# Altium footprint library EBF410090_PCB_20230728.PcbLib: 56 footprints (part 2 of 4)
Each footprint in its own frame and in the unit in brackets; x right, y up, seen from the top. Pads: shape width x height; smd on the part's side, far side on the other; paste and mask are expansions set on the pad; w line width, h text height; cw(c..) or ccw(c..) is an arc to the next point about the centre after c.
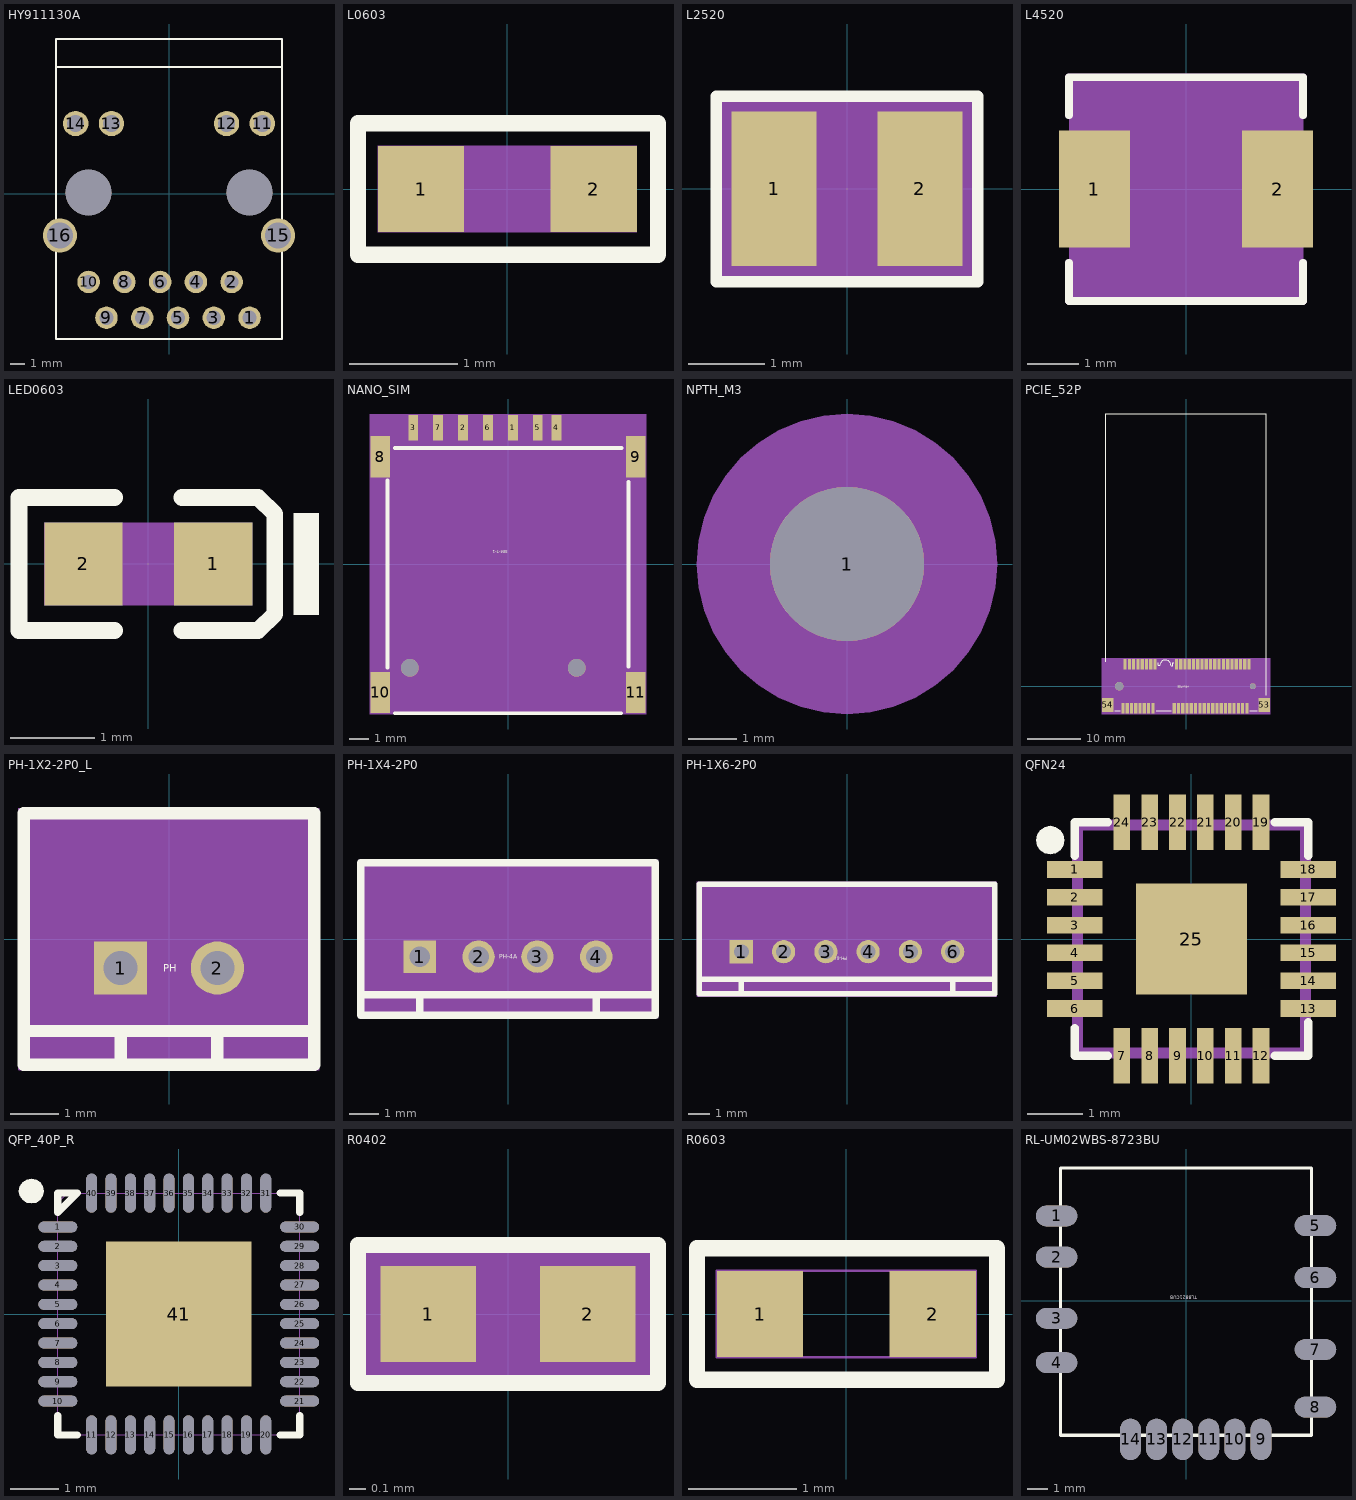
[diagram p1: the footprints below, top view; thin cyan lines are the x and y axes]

## HY911130A [mm] "HY911130A"
pads (18):
  round 1.6 / inner round 1.524 / far side round 1.6 hole 1: 1(5.72,-8.79) 2(4.45,-6.25) 3(3.18,-8.79) 4(1.91,-6.25) 5(0.64,-8.79) 6(-0.63,-6.25) 7(-1.9,-8.79) 8(-3.17,-6.25) 9(-4.44,-8.79)
  round 1.6 hole 1: 10(-5.71,-6.25)
  round 1.8 / inner round 1.524 / far side round 1.8 hole 1.2: 11(6.625,5) 12(4.085,5) 13(-4.085,5) 14(-6.625,5)
  round 2.43 hole 1.83: 15(7.745,-2.95) 16(-7.745,-2.95)
  round 3.25 hole 3.25 unplated: ""(-5.715,0.1) ""(5.715,0.1)
Top Overlay:
  lines w0.15: -8.02,11 8.02,11 8.02,9 ; -8.02,11 -8.02,-10.3 8.02,-10.3 8.02,9 ; -8.02,11 -8.02,9 8.02,9
Bottom Overlay:
  drawing of 14 lines, arcs and shapes, not listed
Mechanical 16:
  text "15" at 6.932,-2.95 h1.02
  text "16" at -8.558,-2.95 h1.02

## L0603 [mil] "L0603"
pads (2):
  rect 31.5x31.5 smd: 1(-31.5,0) 2(31.5,0)
Top Overlay:
  lines w6: -54.5,-24 -54.5,24 55,24 55,-24 -54.5,-24
Top 3D Body:
  region: -47.24,-15.75 -47.24,15.75 47.24,15.75 47.24,-15.75
3D body: height 150, standoff 0, extent -47.24,-15.75 47.24,15.75

## L2520 [mil] "L2520"
pads (2):
  rect 44x80 smd: 1(-37.75,0) 2(37.75,0)
Top Overlay:
  lines w6: -67.68,-48.15 -67.67,-48.15 67.67,-48.15 67.67,47.92 -67.68,47.92 -67.68,-48.15
Top 3D Body:
  region: -65,-45 65,-45 65,45 -65,45
Mechanical 16:
  text "2" at 33.03,0 h11.81
  text "1" at -42.47,0 h11.81
3D body: height 150, standoff 0, extent -65,-45 65,45

## L4520 [mm] "L4520"
pads (2):
  rect 1.4x2.3 smd: 1(-1.803,-0.003) 2(1.798,-0.003)
Top Overlay:
  lines w0.15: -2.303,-1.453 -2.303,-2.202 2.297,-2.202 2.297,-1.453 ; -2.303,1.448 -2.303,2.197 2.297,2.197 2.297,1.448
Top 3D Body:
  region: -2.303,-2.202 -2.303,2.202 2.303,2.202 2.303,-2.202
Mechanical 16:
  text "1" at -2.057,-0.003 h0.64
  text "2" at 1.544,-0.003 h0.64
Top Assembly:
  lines w0.15: -2.303,-1.453 -2.303,-2.202 2.297,-2.202 2.297,-1.453 ; -2.303,1.448 -2.303,2.197 2.297,2.197 2.297,1.448
3D body: height 3.81, standoff 0, extent -2.303,-2.202 2.303,2.202

## LED0603 [mm] "LED0603"
pads (2):
  rect 0.93x0.98 smd: 1(0.77,0) 2(-0.77,0)
Top Overlay:
  dashed: 1.725,-0.6 2.025,-0.6 2.025,0.6 1.725,0.6
  lines w0.2: -0.4,-0.79 -1.535,-0.79 -1.535,0.79 -0.4,0.79 ; 0.4,-0.79 1.3,-0.79 1.5,-0.597 1.5,0.597 1.3,0.79 0.4,0.79
Top 3D Body:
  region: -1.235,-0.49 1.235,-0.49 1.235,0.49 -1.235,0.49
Mechanical 16:
  text "2" at -0.77,-0.254 h0.64
  text "1" at 0.77,-0.254 h0.64
3D body: height 3.81, standoff 0, extent -1.235,-0.49 1.235,0.49

## NANO_SIM [mm] "NANO_SIM"
pads (13):
  rect 0.5x1.3 smd: 1(0.25,6.94) 2(-2.29,6.94) 3(-4.83,6.94) 4(2.47,6.94) 5(1.52,6.94) 6(-1.02,6.94) 7(-3.56,6.94)
  rect 1x2.1 smd: 8(-6.5,5.46) 9(6.5,5.46) 10(-6.5,-6.54) 11(6.5,-6.54)
  round 0.9 hole 0.9 unplated: ""(-5,-5.29) ""(3.5,-5.29)
Top Overlay:
  lines w0.2: -6.145,-5.267 -6.145,4.247 ; -5.756,5.9 5.784,5.9 ; -5.749,-7.6 0,-7.6 5.749,-7.6 ; 6.145,-5.215 6.145,4.189
  text "SIM-7-1" at 0,0.703 h0.15
Top 3D Body:
  region: -7.05,-7.64 -7.05,7.64 7.05,7.64 7.05,-7.64
Mechanical 16:
  text "4" at 2.47,7.062 h0.3
  text "6" at -1.02,7.062 h0.3
  text "7" at -3.56,7.062 h0.3
  text "2" at -2.29,7.062 h0.3
  text "3" at -4.83,7.062 h0.3
  text "5" at 1.52,7.062 h0.3
  text "8" at -6.5,5.582 h0.3
  text "9" at 6.5,5.582 h0.3
  text "10" at -6.5,-6.296 h0.3
  text "11" at 6.5,-6.296 h0.3
  text "1" at 0.25,7.062 h0.3
3D body: height 3.81, standoff 0, extent -7.05,-7.64 7.05,7.64

## NPTH_M3 [mm] "NPTH_M3"
pads (1):
  round 3.2 / inner round 1.524 / far side round 3.2 hole 3.2 unplated: 1(0,0)
Top Overlay:
  text "NPTH_M3" at -0.376,0.631 h0.15
Top 3D Body:
  region: 3.11,0 3.071,0.486 2.957,0.961 2.771,1.412 2.516,1.828 2.199,2.199 1.828,2.516 1.412,2.771 0.961,2.957 0.486,3.071 0,3.11 -0.486,3.071 -0.961,2.957 -1.412,2.771 -1.551,2.686 -1.828,2.516 -2.199,2.199 -2.516,1.828 -2.771,1.412 -2.957,0.961 -3.071,0.486 -3.11,0 -3.071,-0.486 -2.957,-0.961 -2.771,-1.412 -2.516,-1.828 -2.199,-2.199 -1.828,-2.516 -1.551,-2.686 -1.412,-2.771 -0.961,-2.957 -0.486,-3.071 0,-3.11 0.486,-3.071 0.961,-2.957 1.412,-2.771 1.828,-2.516 2.199,-2.199 2.516,-1.828 2.771,-1.412 2.957,-0.961 3.071,-0.486
Mechanical 16:
  text "1" at -0.254,0 h0.64
3D body: height 3.81, standoff 0, extent -3.11,-3.11 3.11,3.11

## PCIE_52P [mm] "PCIE_52P"
pads (56):
  rect 0.6x2 smd: 1(-11.8,-4.1) 2(-11.4,4.1) 3(-11,-4.1) 4(-10.6,4.1) 5(-10.2,-4.1) 6(-9.8,4.1) 7(-9.4,-4.1) 8(-9,4.1) 9(-8.6,-4.1) 10(-8.2,4.1) 11(-7.8,-4.1) 12(-7.4,4.1) 13(-7,-4.1) 14(-6.6,4.1) 15(-6.2,-4.1) 16(-5.8,4.1) 17(-2.2,-4.1) 18(-1.8,4.1) 19(-1.4,-4.1) 20(-1,4.1) 21(-0.6,-4.1) 22(-0.2,4.1) 23(0.2,-4.1) 24(0.6,4.1) 25(1,-4.1) 26(1.4,4.1) 27(1.8,-4.1) 28(2.2,4.1) 29(2.6,-4.1) 30(3,4.1) 31(3.4,-4.1) 32(3.8,4.1) 33(4.2,-4.1) 34(4.6,4.1) 35(5,-4.1) 36(5.4,4.1) 37(5.8,-4.1) 38(6.2,4.1) 39(6.6,-4.1) 40(7,4.1) 41(7.4,-4.1) 42(7.8,4.1) 43(8.2,-4.1) 44(8.6,4.1) 45(9,-4.1) 46(9.4,4.1) 47(9.8,-4.1) 48(10.2,4.1) 49(10.6,-4.1) 50(11,4.1) 51(11.4,-4.1) 52(11.8,4.1)
  rect 2.15x2.6 smd: 53(14.65,-3.5) 54(-14.65,-3.5)
  round 1.6 hole 1.6 unplated: ""(-12.5,0)
  round 1.1 hole 1.1 unplated: ""(12.5,0)
Top Overlay:
  lines w0.2: -15,4.6 -15,50.949 15,50.949 15,4.6 ; -13.3,-4.6 -12.3,-4.6 ; -5.6,-4.6 -2.8,-4.6 ; -5.326,4.387 -5.165,4.387 -5.165,3.883 -4.887,3.883 cw(c-3.843,3.859) -2.8,3.859 -2.8,3.847 -2.474,3.847 -2.474,4.38 -2.29,4.38 ; 11.9,-4.6 13.3,-4.6 ; 15,-1.7 15,4.6 ; 15,4.6 15,4.6
  text "MINI-PCIE" at 0.549,0.076 h0.15
Top 3D Body:
  region: -15.8,-5.2 -15.8,5.2 15.8,5.2 15.8,-5.2
Mechanical 16:
  text "42" at 8.288,4.1 h0.3
  text "3" at -10.756,-4.1 h0.3
  text "6" at -9.556,4.1 h0.3
  text "48" at 10.688,4.1 h0.3
  text "45" at 9.488,-4.1 h0.3
  text "47" at 10.288,-4.1 h0.3
  text "49" at 11.088,-4.1 h0.3
  text "51" at 11.888,-4.1 h0.3
  text "17" at -1.712,-4.1 h0.3
  text "16" at -5.312,4.1 h0.3
  text "5" at -9.956,-4.1 h0.3
  text "28" at 2.688,4.1 h0.3
  text "30" at 3.488,4.1 h0.3
  text "46" at 9.888,4.1 h0.3
  text "44" at 9.088,4.1 h0.3
  text "19" at -0.912,-4.1 h0.3
  text "32" at 4.288,4.1 h0.3
  text "14" at -6.112,4.1 h0.3
  text "22" at 0.288,4.1 h0.3
  text "10" at -7.712,4.1 h0.3
  text "33" at 4.688,-4.1 h0.3
  text "1" at -11.556,-4.1 h0.3
  text "7" at -9.156,-4.1 h0.3
  text "31" at 3.888,-4.1 h0.3
  text "20" at -0.512,4.1 h0.3
  text "12" at -6.912,4.1 h0.3
  text "25" at 1.488,-4.1 h0.3
  text "23" at 0.688,-4.1 h0.3
  text "11" at -7.312,-4.1 h0.3
  text "13" at -6.512,-4.1 h0.3
  text "50" at 11.488,4.1 h0.3
  text "40" at 7.488,4.1 h0.3
  text "34" at 5.088,4.1 h0.3
  text "26" at 1.888,4.1 h0.3
  text "18" at -1.312,4.1 h0.3
  text "4" at -10.356,4.1 h0.3
  text "43" at 8.688,-4.1 h0.3
  text "37" at 6.288,-4.1 h0.3
  text "35" at 5.488,-4.1 h0.3
  text "29" at 3.088,-4.1 h0.3
  text "27" at 2.288,-4.1 h0.3
  text "21" at -0.112,-4.1 h0.3
  text "15" at -5.712,-4.1 h0.3
  text "9" at -8.356,-4.1 h0.3
  text "54" at -14.162,-3.5 h0.3
  text "53" at 15.138,-3.5 h0.3
  text "8" at -8.756,4.1 h0.3
  text "52" at 12.288,4.1 h0.3
  text "24" at 1.088,4.1 h0.3
  text "2" at -11.156,4.1 h0.3
  text "41" at 7.888,-4.1 h0.3
  text "39" at 7.088,-4.1 h0.3
  text "38" at 6.688,4.1 h0.3
  text "36" at 5.888,4.1 h0.3
Top Assembly:
  dashed: -15.8,5.2 -15.8,-5.2 15.8,-5.2 15.8,5.2
3D body: height 3.81, standoff 0, extent -15.8,-5.2 15.8,5.2

## PH-1X2-2P0_L [mm] "PH-1X2-2P0_L"
pads (2):
  rect 1.1x1.1 / inner round 1.524 / far side rect 1.1x1.1 hole 0.7: 1(-1,-0.6)
  round 1.1 / inner round 1.524 / far side round 1.1 hole 0.7: 2(1,-0.6)
Top Overlay:
  lines w0.254: -3,-1.9 3,-1.9 ; -1,-2.6 -1,-1.9 ; 1,-2.6 1,-1.9 ; -3,-2.6 3,-2.6 3,2.6 -3,2.6 -3,-2.6
  text "PH" at -0.122,-0.676 h0.15
Bottom Overlay:
  lines w0.6: 0,-1.1 0,-0.1
Top 3D Body:
  region: -3.1,2.7 -3.1,-2.7 3.1,-2.7 3.1,2.7
Mechanical 16:
  text "1" at -1.254,-0.6 h0.64
  text "2" at 0.746,-0.6 h0.64
Top Assembly:
  lines w0.025: -3.1,-2.7 3.1,-2.7 3.1,2.7 -3.1,2.7 -3.1,-2.7
3D body: height 3.81, standoff 0, extent -3.1,-2.7 3.1,2.7

## PH-1X4-2P0 [mm] "PH-1X4-2P0"
pads (4):
  rect 1.1x1.1 / inner round 1.524 / far side rect 1.1x1.1 hole 0.7: 1(-3,-0.6)
  round 1.1 / inner round 1.524 / far side round 1.1 hole 0.7: 2(-1,-0.6) 3(1,-0.6)
  round 1.1 hole 0.7: 4(3,-0.6)
Top Overlay:
  lines w0.254: -5,-1.9 5,-1.9 ; -3,-2.6 -3,-1.9 ; 3,-2.6 3,-1.9 ; -5,-2.6 5,-2.6 5,2.6 -5,2.6 -5,-2.6
  text "PH-4A" at -0.305,-0.676 h0.15
Top 3D Body:
  region: -5.1,2.7 -5.1,-2.7 5.1,-2.7 5.1,2.7
3D body: height 3.81, standoff 0, extent -5.1,-2.7 5.1,2.7

## PH-1X6-2P0 [mm] "PH-1X6-2P0"
pads (6):
  rect 1.1x1.1 / inner round 1.524 / far side rect 1.1x1.1 hole 0.7: 1(-5,-0.6)
  round 1.1 hole 0.7: 2(-3,-0.6) 4(1,-0.6) 6(5,-0.6)
  round 1.1 / inner round 1.524 / far side round 1.1 hole 0.7: 3(-1,-0.6) 5(3,-0.6)
Top Overlay:
  lines w0.254: -7,-1.9 7,-1.9 ; -5,-2.6 -5,-1.9 ; 5,-2.6 5,-1.9 ; -7,-2.6 -7,2.6 7,2.6 7,-2.6 -7,-2.6
  text "PH-6A" at 0,-0.829 h0.15
Bottom Overlay:
  lines w0.5: -4,-1.1 -4,-0.1 ; -2,-1.1 -2,-0.1 ; 0,-1.1 0,-0.1 ; 2,-1.1 2,-0.1 ; 4,-1.1 4,-0.1
Top 3D Body:
  region: -7.1,2.7 -7.1,-2.7 7.1,-2.7 7.1,2.7
Mechanical 16:
  text "5" at 3,-0.854 h0.64
  text "1" at -5,-0.854 h0.64
  text "2" at -3,-0.854 h0.64
  text "4" at 1,-0.854 h0.64
  text "6" at 5,-0.854 h0.64
  text "3" at -1,-0.854 h0.64
Top Assembly:
  lines w0.025: -7.1,-2.7 7.1,-2.7 7.1,2.7 -7.1,2.7 -7.1,-2.7
3D body: height 3.81, standoff 0, extent -7.1,-2.7 7.1,2.7

## QFN24 [mm] "QFN24"
pads (25):
  rect 1x0.3 smd: 1(-2.1,1.25) 2(-2.1,0.75) 3(-2.1,0.25) 4(-2.1,-0.25) 5(-2.1,-0.75) 6(-2.1,-1.25) 13(2.1,-1.25) 14(2.1,-0.75) 15(2.1,-0.25) 16(2.1,0.25) 17(2.1,0.75) 18(2.1,1.25)
  rect 0.3x1 smd: 7(-1.25,-2.1) 8(-0.75,-2.1) 9(-0.25,-2.1) 10(0.25,-2.1) 11(0.75,-2.1) 12(1.25,-2.1) 19(1.25,2.1) 20(0.75,2.1) 21(0.25,2.1) 22(-0.25,2.1) 23(-0.75,2.1) 24(-1.25,2.1)
  rect 2x2 smd: 25(0,0)
Top Overlay:
  dashed: -2.54,1.523 -2.442,1.542 -2.36,1.598 -2.305,1.68 -2.285,1.778 -2.305,1.875 -2.323,1.903 -2.36,1.958 -2.442,2.013 -2.54,2.033 -2.638,2.013 -2.72,1.958 -2.757,1.903 -2.775,1.875 -2.795,1.778 -2.775,1.68 -2.72,1.598 -2.638,1.542
  lines w0.15: -2.1,-1.6 -2.1,-2.1 -1.5,-2.1 ; -2.1,1.5 -2.1,2.1 -1.5,2.1 ; 1.5,-2.1 2.1,-2.1 2.1,-1.5 ; 1.5,2.1 2.1,2.1 2.1,1.5
  text "CH334F" at 0,0.29 h0.15
Mechanical 16:
  text "25" at 0,0.305 h0.38
  text "1" at -2.1,1.402 h0.38
Top Assembly:
  lines w0.2: -2.05,-2.05 -2.05,2.05 2.05,2.05 2.05,-2.05 -2.05,-2.05

## QFP_40P_R [mil] "QFP_40P_R"
pads (41):
  oval 31.5x8.66 smd: 1(-98.43,70.87) 2(-98.43,55.12) 3(-98.43,39.37) 4(-98.43,23.62) 5(-98.43,7.87) 6(-98.43,-7.87) 7(-98.43,-23.62) 8(-98.43,-39.37) 9(-98.43,-55.12) 10(-98.43,-70.87) 21(98.43,-70.87) 22(98.43,-55.12) 23(98.43,-39.37) 24(98.43,-23.62) 25(98.43,-7.87) 26(98.43,7.87) 27(98.43,23.62) 28(98.43,39.37) 29(98.43,55.12) 30(98.43,70.87)
  oval 8.66x31.5 smd: 11(-70.87,-98.43) 12(-55.12,-98.43) 13(-39.37,-98.43) 14(-23.62,-98.43) 15(-7.87,-98.43) 16(7.87,-98.43) 17(23.62,-98.43) 18(39.37,-98.43) 19(55.12,-98.43) 20(70.87,-98.43) 31(70.87,98.43) 32(55.12,98.43) 33(39.37,98.43) 34(23.62,98.43) 35(7.87,98.43) 36(-7.87,98.43) 37(-23.62,98.43) 38(-39.37,98.43) 39(-55.12,98.43) 40(-70.87,98.43)
  rect 118.11x118.11 smd: 41(0,0)
Top Overlay:
  dashed: -109.96,99.99 -110.72,96.15 -112.9,92.9 -116.15,90.72 -119.99,89.96 -123.83,90.72 -124.92,91.45 -127.08,92.9 -129.26,96.15 -130.02,99.99 -129.26,103.83 -127.08,107.08 -124.92,108.53 -123.83,109.26 -119.99,110.02 -116.15,109.26 -112.9,107.08 -110.72,103.83
  lines w5.91: -98.43,-82.68 -98.43,-98.43 -82.68,-98.43 ; 82.68,-98.43 98.43,-98.43 98.43,-82.68 ; 82.68,98.43 98.43,98.43 98.43,82.68 ; -98.43,82.68 -82.68,98.43 -98.43,98.43 -98.43,82.68
Mechanical 16:
  text "41" at -16,0 h20
Top Assembly:
  lines w1: -98.43,90.55 -90.55,98.43 ; -98.43,-98.43 -98.43,98.43 98.43,98.43 98.43,-98.43 -98.43,-98.43

## R0402 [mm] "R0402"
pads (2):
  rect 0.599x0.599 smd: 1(-0.5,0) 2(0.5,0)
Top Overlay:
  lines w0.102: -0.94,-0.432 -0.94,0.432 0.94,0.432 0.94,-0.432 -0.94,-0.432
Top 3D Body:
  region: 0.94,0.432 0.94,-0.432 -0.94,-0.432 -0.94,0.432
Top Assembly:
  dashed: -0.94,-0.432 -0.94,0.432 0.94,0.432 0.94,-0.432
3D body: height 3.81, standoff 0, extent -0.94,-0.432 0.94,0.432

## R0603 [mil] "R0603"
pads (2):
  rect 31.5x31.5 smd: 1(-31.5,0) 2(31.5,0)
Top Overlay:
  lines w6: -54.5,-24 -54.5,24 55,24 55,-24 -54.5,-24
Top 3D Body:
  lines w1: -47.24,-15.75 47.24,-15.75 47.24,15.75 -47.24,15.75 -47.24,-15.75

## RL-UM02WBS-8723BU [mm] "RL-UM02WBS-8723BU"
pads (14):
  oval 2x1 smd: 1(-6.3,4.122) 2(-6.3,2.122) 3(-6.3,-0.858) 4(-6.3,-3.018) 5(6.3,3.652) 6(6.3,1.122) 7(6.3,-2.378) 8(6.3,-5.178)
  oval 1x2 smd: 9(3.65,-6.748) 10(2.38,-6.748) 11(1.11,-6.748) 12(-0.16,-6.748) 13(-1.43,-6.748) 14(-2.7,-6.748)
Top Overlay:
  lines w0.15: -6.1,-6.548 -6.1,6.452 6.1,6.452 6.1,-6.548 -6.1,-6.548
  text "TL8821CUB" at 0.549,0.228 h0.15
